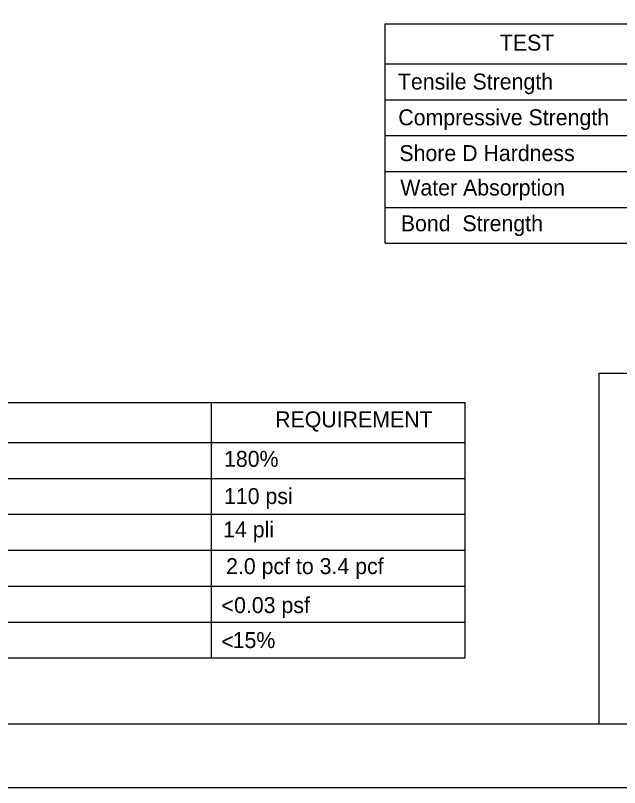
# Model space of a CAD drawing. Extents: x -125.5 to -89.4, y -5.1 to 16.9.
# Drawn here: x -107.48 to -102.74, y -5.07 to 0.99 of the extents above; entities that cross this region are included whole.
import ezdxf

# ---------------------------------------------------------------- set-up
doc = ezdxf.new("R2010")
doc.units = 0
for name, color, linetype in [('BR_BORDER LINES', 7, 'Continuous'), ('BR_TABLE LINES', 7, 'Continuous'), ('BR_TEXT', 7, 'Continuous'), ('Level 31', 7, 'Continuous')]:
    doc.layers.add(name, color=color, linetype=linetype)

msp = doc.modelspace()

# ---------------------------------------------------------------- linework, layer by layer
at = {"layer": 'BR_BORDER LINES'}
for p, q in [((-102.8989, -1.8161), (-97.5337, -1.8161)), ((-102.8989, -4.5661), (-102.8989, -1.8161)), ((-123.6994, -4.5662), (-90.0334, -4.5662))]:
    msp.add_line(p, q, dxfattribs=at)
at = {"layer": 'BR_TABLE LINES'}
for p, q in [((-104.5796, 0.9224), (-99.3257, 0.9224)), ((-104.5796, -0.7981), (-104.5796, 0.9224)), ((-104.5796, 0.6092), (-99.3257, 0.6092)), ((-104.5796, 0.3278), (-99.3257, 0.3278)), ((-104.5796, 0.0463), (-99.3257, 0.0463)), ((-104.5796, -0.2352), (-99.3257, -0.2352)), ((-104.5796, -0.5167), (-99.3257, -0.5167)), ((-104.5796, -0.7981), (-99.3257, -0.7981)), ((-113.8169, -2.0474), (-103.9518, -2.0474)), ((-105.9422, -4.0493), (-105.9422, -2.0474)), ((-103.9518, -4.0493), (-103.9518, -2.0474)), ((-113.8169, -2.3605), (-103.9518, -2.3605)), ((-113.8169, -2.642), (-103.9518, -2.642)), ((-113.8169, -2.9234), (-103.9518, -2.9234)), ((-113.8169, -3.2049), (-103.9518, -3.2049)), ((-113.8169, -3.4864), (-103.9518, -3.4864)), ((-113.8169, -3.7679), (-103.9518, -3.7679)), ((-113.8169, -4.0493), (-103.9518, -4.0493))]:
    msp.add_line(p, q, dxfattribs=at)
at = {"layer": 'Level 31'}
msp.add_lwpolyline([(-125.5328, -5.0661), (-89.5328, -5.0661), (-89.5328, 16.9339), (-125.5328, 16.9339)], close=True, dxfattribs=at)

# ---------------------------------------------------------------- texts
at = {"layer": 'BR_TEXT'}
for s, p in [('TEST', (-103.6792, 0.7129)), ('Tensile Strength', (-104.4791, 0.4079)), ('Compressive Strength', (-104.4759, 0.1274)), ('Shore D Hardness', (-104.4674, -0.1532)), ('Water Absorption', (-104.4603, -0.4233)), ('Bond  Strength', (-104.4564, -0.7039)), ('REQUIREMENT', (-105.4421, -2.241)), ('180% ', (-105.8432, -2.551)), ('110 psi ', (-105.8432, -2.8427)), ('14 pli ', (-105.8502, -3.1045)), ('2.0 pcf to 3.4 pcf', (-105.827, -3.3922)), (' 0.03 psf', (-105.8108, -3.6976)), ('<', (-105.8638, -3.7005)), (' 15% ', (-105.8217, -3.9722)), ('<', (-105.8638, -3.9817))]:
    msp.add_text(s, height=0.125, dxfattribs=at).set_placement(p)

doc.saveas('drawing.dxf')
